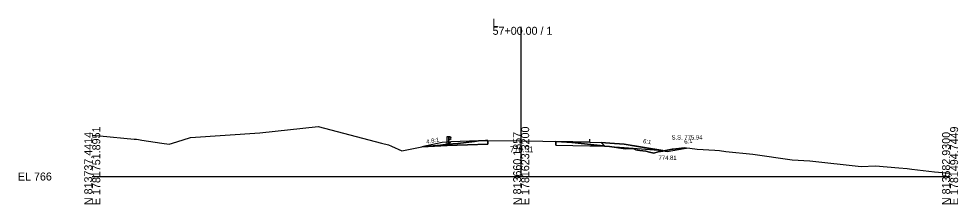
# Model space of a CAD drawing. Extents: x -26 to 7903, y -10 to 9573.
# Drawn here: x 1974.3 to 2302.8, y 7990.3 to 8055.2 of the extents above; entities that cross this region are included whole.
import ezdxf

# ---------------------------------------------------------------- set-up
doc = ezdxf.new("R2010")
doc.units = 0
for name, color, linetype in [('Exist Cross Section Cell', 7, 'Continuous'), ('Exist XS Center Line Elevation Label', 7, 'Continuous'), ('Exist XS Ground Line', 7, 'Continuous'), ('Prop XS Ditch Slope Text', 7, 'Continuous'), ('Prop XS Ditch Standard Text', 7, 'Continuous'), ('Prop XS Dump Level', 7, 'Continuous'), ('Prop XS Earthwork Shape', 7, 'Continuous'), ('Prop XS EOT Tick Mark', 7, 'Continuous'), ('Prop XS Finish Grade', 7, 'Continuous'), ('Prop XS Finish Grade Earthwork', 7, 'Continuous'), ('Prop XS Finish Grade Paved Shoulder', 7, 'Continuous'), ('Prop XS Finish Grade Pavement', 7, 'Continuous'), ('Prop XS Guardrail', 7, 'Continuous'), ('Prop XS Hydro Typical Ditch Data', 7, 'Continuous'), ('Prop XS Pvmt Edge Slope', 7, 'Continuous'), ('Prop XS Side Slope Text', 7, 'Continuous'), ('Prop XS SS Elevation Text', 7, 'Continuous'), ('Prop XS Subgrade Earthwork', 7, 'Continuous'), ('Scratch_Level_3', 7, 'Continuous'), ('Scratch_Level_6', 7, 'Continuous')]:
    doc.layers.add(name, color=color, linetype=linetype)

msp = doc.modelspace()

# ---------------------------------------------------------------- linework, layer by layer
at = {"layer": 'Exist Cross Section Cell'}
for p, q in [((2150, 8000), (2150, 8052.4)), ((2000, 8000), (2150, 8000)), ((2150, 8000), (2300, 8000))]:
    msp.add_line(p, q, dxfattribs=at)
at = {"layer": 'Exist XS Ground Line'}
for p, q in [((2058.59, 8015.31), (2078.96, 8017.47)), ((2078.96, 8017.47), (2101.16, 8011.68)), ((2000, 8014.53), (2002.6, 8014.29)), ((2002.6, 8014.29), (2014.68, 8013.12)), ((2014.68, 8013.12), (2015.43, 8013.03)), ((2015.43, 8013.03), (2016.19, 8012.92)), ((2016.19, 8012.92), (2017.33, 8012.75)), ((2029.63, 8012.14), (2034.3, 8013.6)), ((2034.3, 8013.6), (2058.59, 8015.31)), ((2017.33, 8012.75), (2024.3, 8011.67)), ((2024.3, 8011.67), (2026.84, 8011.3)), ((2026.84, 8011.3), (2029.63, 8012.14)), ((2101.16, 8011.68), (2103.56, 8011.05)), ((2103.56, 8011.05), (2104.66, 8010.62)), ((2104.66, 8010.62), (2108.29, 8009.02)), ((2108.29, 8009.02), (2115.21, 8010.38)), ((2115.21, 8010.38), (2121.76, 8011.02)), ((2121.76, 8011.02), (2124.23, 8011.3)), ((2124.23, 8011.3), (2127.89, 8011.6)), ((2127.89, 8011.6), (2133.7, 8012.3)), ((2133.7, 8012.3), (2135.07, 8012.44)), ((2135.07, 8012.44), (2137.51, 8012.58)), ((2137.51, 8012.58), (2138.37, 8012.63)), ((2138.37, 8012.63), (2149.26, 8012.52)), ((2149.26, 8012.52), (2149.61, 8012.52)), ((2149.61, 8012.52), (2150, 8012.51)), ((2150, 8012.51), (2157.57, 8012.36)), ((2157.57, 8012.36), (2162.11, 8012.27)), ((2162.11, 8012.27), (2165.98, 8012.06)), ((2165.98, 8012.06), (2166.68, 8011.98)), ((2166.68, 8011.98), (2171.02, 8011.54)), ((2171.02, 8011.54), (2178.77, 8010.73)), ((2178.77, 8010.73), (2180.86, 8010.46)), ((2180.86, 8010.46), (2186.46, 8009.73)), ((2186.46, 8009.73), (2187.8, 8009.75)), ((2187.8, 8009.75), (2189.11, 8009.8)), ((2189.11, 8009.8), (2190.05, 8009.39)), ((2203.19, 8009.61), (2207.02, 8009.99)), ((2207.02, 8009.99), (2208.93, 8009.87)), ((2208.93, 8009.87), (2211.53, 8009.63)), ((2211.53, 8009.63), (2217.72, 8009.21)), ((2190.05, 8009.39), (2190.7, 8009.26)), ((2190.7, 8009.26), (2191.48, 8009.14)), ((2191.48, 8009.14), (2193.58, 8008.9)), ((2193.58, 8008.9), (2194.93, 8008.56)), ((2194.93, 8008.56), (2196.36, 8008.22)), ((2196.36, 8008.22), (2197.87, 8008.59)), ((2197.87, 8008.59), (2199.53, 8008.92)), ((2199.53, 8008.92), (2202.76, 8009.56)), ((2202.76, 8009.56), (2203.19, 8009.61)), ((2217.72, 8009.21), (2219.31, 8009.06)), ((2219.31, 8009.06), (2221.57, 8008.81)), ((2221.57, 8008.81), (2231.04, 8007.79)), ((2231.04, 8007.79), (2244.77, 8005.86)), ((2244.77, 8005.86), (2250.94, 8005.52)), ((2250.94, 8005.52), (2268.85, 8003.54)), ((2268.85, 8003.54), (2273.94, 8003.7)), ((2273.94, 8003.7), (2282.06, 8003.03)), ((2282.06, 8003.03), (2285.01, 8002.78)), ((2285.01, 8002.78), (2286.67, 8002.56)), ((2286.67, 8002.56), (2294.5, 8001.64)), ((2294.5, 8001.64), (2300, 8001.12))]:
    msp.add_line(p, q, dxfattribs=at)
at = {"layer": 'Prop XS Dump Level'}
for p, q in [((2162.12, 8012.27), (2174, 8012.03)), ((2174, 8012.03), (2162.12, 8012.27))]:
    msp.add_line(p, q, dxfattribs=at)
at = {"layer": 'Prop XS Earthwork Shape'}
for points in [[(2124.12, 8010.81), (2115.21, 8010.38), (2121.76, 8011.02), (2124.23, 8011.3), (2127.89, 8011.6), (2133.7, 8012.3), (2135.07, 8012.44), (2137.51, 8012.58), (2138.37, 8012.63), (2138.37, 8011.38)], [(2162.11, 8011.02), (2174, 8010.78), (2178, 8010.7), (2179.19, 8010.68), (2178.77, 8010.73), (2171.02, 8011.54), (2166.68, 8011.98), (2165.98, 8012.06), (2162.11, 8012.27)], [(2199.54, 8009.06), (2199.9, 8009), (2199.53, 8008.92), (2197.87, 8008.59), (2196.36, 8008.22), (2194.93, 8008.56), (2193.58, 8008.9), (2191.48, 8009.14), (2190.7, 8009.26), (2190.05, 8009.39), (2189.11, 8009.8), (2187.8, 8009.75), (2186.46, 8009.73), (2180.86, 8010.46), (2179.19, 8010.68), (2179.28, 8010.68), (2181, 8010.54), (2186, 8010.14)], [(2199.9, 8009), (2201, 8008.81), (2207, 8009.81), (2207.77, 8009.94), (2207.02, 8009.99), (2203.19, 8009.61), (2202.76, 8009.56)]]:
    msp.add_lwpolyline(points, close=True, dxfattribs=at)
at = {"layer": 'Prop XS EOT Tick Mark'}
msp.add_line((2174, 8012.03), (2174, 8013.03), dxfattribs=at)
at = {"layer": 'Prop XS Finish Grade'}
for p, q in [((2122.42, 8011.87), (2115.21, 8010.38)), ((2125.42, 8012.11), (2122.42, 8011.87)), ((2178, 8011.95), (2181, 8011.71)), ((2181, 8011.71), (2186, 8011.31)), ((2186, 8011.31), (2199.54, 8009.06))]:
    msp.add_line(p, q, dxfattribs=at)
at = {"layer": 'Prop XS Finish Grade Earthwork'}
for p, q in [((2201, 8008.81), (2207, 8009.81)), ((2207, 8009.81), (2207.77, 8009.94)), ((2199.54, 8009.06), (2201, 8008.81))]:
    msp.add_line(p, q, dxfattribs=at)
at = {"layer": 'Prop XS Finish Grade Paved Shoulder'}
msp.add_line((2174, 8012.03), (2178, 8011.95), dxfattribs=at)
at = {"layer": 'Prop XS Finish Grade Pavement'}
for p, q in [((2138.37, 8012.63), (2125.42, 8012.11)), ((2162.11, 8012.27), (2174, 8012.03))]:
    msp.add_line(p, q, dxfattribs=at)
at = {"layer": 'Prop XS Guardrail'}
for p, q in [((2124.1, 8013.99), (2124.6, 8013.99)), ((2124.1, 8011.49), (2124.1, 8013.99)), ((2124.6, 8013.99), (2125.1, 8013.99)), ((2124.6, 8013.99), (2124.6, 8011.49)), ((2125.1, 8013.99), (2125.39, 8013.79)), ((2125.39, 8013.67), (2125.1, 8013.47)), ((2125.1, 8013.47), (2125.1, 8013.37)), ((2125.1, 8013.37), (2125.39, 8013.17)), ((2125.39, 8013.05), (2125.1, 8012.85)), ((2125.39, 8013.79), (2125.42, 8013.73)), ((2125.42, 8013.73), (2125.39, 8013.67)), ((2125.39, 8013.17), (2125.42, 8013.11)), ((2125.42, 8013.11), (2125.39, 8013.05)), ((2125.1, 8012.85), (2124.6, 8012.85))]:
    msp.add_line(p, q, dxfattribs=at)
at = {"layer": 'Prop XS Hydro Typical Ditch Data'}
for p, q in [((2186, 8011.31), (2201, 8008.81)), ((2201, 8008.81), (2207, 8009.81)), ((2207, 8009.81), (2207.77, 8009.94))]:
    msp.add_line(p, q, dxfattribs=at)
at = {"layer": 'Prop XS Pvmt Edge Slope'}
for p, q in [((2125.42, 8012.11), (2124.12, 8010.81)), ((2178, 8011.95), (2179.28, 8010.68))]:
    msp.add_line(p, q, dxfattribs=at)
at = {"layer": 'Prop XS Subgrade Earthwork'}
for p, q in [((2124.12, 8010.81), (2115.21, 8010.38)), ((2138.37, 8011.38), (2124.12, 8010.81)), ((2138.37, 8011.38), (2138.37, 8012.63)), ((2162.11, 8011.02), (2162.11, 8012.27)), ((2162.11, 8011.02), (2174, 8010.78)), ((2174, 8010.78), (2178, 8010.7)), ((2178, 8010.7), (2179.28, 8010.68)), ((2179.28, 8010.68), (2181, 8010.54)), ((2181, 8010.54), (2186, 8010.14)), ((2186, 8010.14), (2199.54, 8009.06))]:
    msp.add_line(p, q, dxfattribs=at)
at = {"layer": 'Scratch_Level_3'}
for p, q in [((2122.42, 8011.87), (2115.21, 8010.38)), ((2115.21, 8010.38), (2124.12, 8010.81)), ((2125.42, 8012.11), (2122.42, 8011.87)), ((2124.12, 8010.81), (2125.42, 8012.11)), ((2181, 8011.71), (2178, 8011.95)), ((2178, 8011.95), (2179.28, 8010.68)), ((2179.28, 8010.68), (2181, 8010.54)), ((2186, 8011.31), (2181, 8011.71)), ((2181, 8010.54), (2186, 8010.14)), ((2199.54, 8009.06), (2186, 8011.31)), ((2186, 8010.14), (2199.54, 8009.06))]:
    msp.add_line(p, q, dxfattribs=at)
at = {"layer": 'Scratch_Level_6'}
for points in [[(2138.37, 8011.38), (2138.37, 8012.63), (2137.51, 8012.58), (2135.07, 8012.44), (2133.7, 8012.3), (2127.89, 8011.6), (2124.23, 8011.3), (2121.76, 8011.02), (2115.21, 8010.38), (2124.12, 8010.81)], [(2178, 8010.7), (2179.19, 8010.68), (2178.77, 8010.73), (2171.02, 8011.54), (2166.68, 8011.98), (2165.98, 8012.06), (2162.11, 8012.27), (2162.11, 8011.02), (2174, 8010.78)]]:
    msp.add_lwpolyline(points, close=True, dxfattribs=at)

# ---------------------------------------------------------------- texts
at = {"layer": 'Exist Cross Section Cell'}
for s, p in [('57+00.00 / 1', (2140, 8049.6)), ('L', (2140, 8052.4)), ('EL 766', (1974, 7998.6))]:
    msp.add_text(s, height=2.8, dxfattribs=at).set_placement(p)
for s, p in [('E 1781751.8951', (2002.8, 7990)), ('E 1781623.3200', (2152.8, 7990)), ('E 1781494.7449', (2302.8, 7990)), ('N 813737.4414', (2000, 7990)), ('N 813660.1857', (2150, 7990)), ('N 813582.9300', (2300, 7990))]:
    msp.add_text(s, height=2.8, rotation=90, dxfattribs=at).set_placement(p)
at = {"layer": 'Exist XS Center Line Elevation Label'}
msp.add_text('778.51', height=2, dxfattribs=at).set_placement((2146.08, 8008.51))
at = {"layer": 'Prop XS Ditch Slope Text'}
for s, rotation, p in [('4.8:1', 10.1372, (2116.93, 8011.41)), ('6:1', 350.5377, (2192.55, 8011.74))]:
    msp.add_text(s, height=1.5, rotation=rotation, dxfattribs=at).set_placement(p)
at = {"layer": 'Prop XS Ditch Standard Text'}
msp.add_text('774.81', height=1.5, dxfattribs=at).set_placement((2198.03, 8005.81))
at = {"layer": 'Prop XS Dump Level'}
for s, height, p in [('Eop', 0.3, (2162.11, 8011.97)), ('Case4', 0.04, (2186, 8011.27))]:
    msp.add_text(s, height=height, dxfattribs=at).set_placement(p)
at = {"layer": 'Prop XS Side Slope Text'}
msp.add_text('6:1', height=1.5, rotation=9.4623, dxfattribs=at).set_placement((2207.14, 8011.36))
at = {"layer": 'Prop XS SS Elevation Text'}
msp.add_text('S.S. 775.94', height=1.5, dxfattribs=at).set_placement((2202.58, 8012.94))

doc.saveas('drawing.dxf')
